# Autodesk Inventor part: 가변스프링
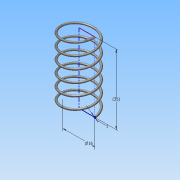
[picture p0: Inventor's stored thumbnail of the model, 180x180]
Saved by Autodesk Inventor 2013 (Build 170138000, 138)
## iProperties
Created: 2016-05
Part Number: 가변스프링
Material: 스테인리스강
Document SubType Name: Modeling
Designer: Administrator
Density: 8.08 g/cm^3
Mass: 1.89963 g
Surface Area: 9.46581 cm^2
Volume: 0.235103 cm^3
Author: Administrator
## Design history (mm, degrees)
sketch "스케치1"
  geometry: L1 (0, 0)-(8, 0); L2 (8, 0)-(8, 28.5); L3 (8, 28.5)-(0, 28.5); L4 (0, 28.5)-(0, 0); C1 r 0.5 at (8, 0)
  constraints: 8 end point, 2 parallel, 1 centre point, 1 coincident, 1 horizontal, 1 perpendicular
  dimensions: "d0" = 16 diameter of L2 L4; "d2" = 28.5 distance between parallel lines of L3 L1 (derived); "d3" = 1 diameter of C1
feature "코일1" sketch "스케치1" pitch "d4" = 10; turns "d6" = 6; dims "d5" = 28.5 (= d2), "d7" = 0, angle "d8" = 90 deg, angle "d9" = 90 deg, "d10" = 0, "d11" = 0
node "작업 평면1"
feature "분할1"
feature "분할2"
node "솔리드1"
other parameters: "d12" = 90 deg
